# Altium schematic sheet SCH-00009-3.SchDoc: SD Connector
size A4
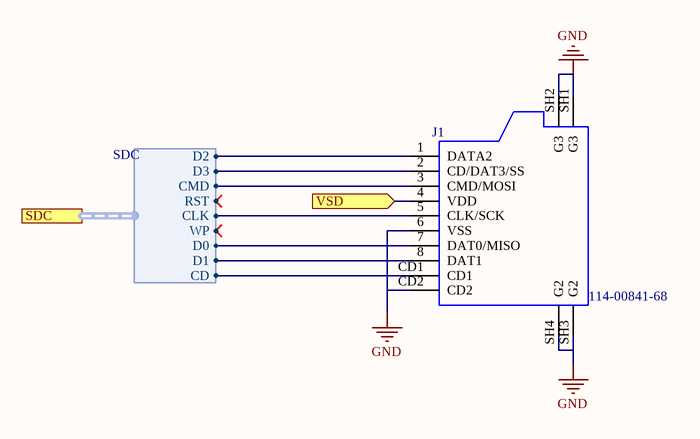
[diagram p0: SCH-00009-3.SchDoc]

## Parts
J1  114-00841-68  [AMPHENOL_114-00841-68]

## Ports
SDC (harness SDC), VSD (in)

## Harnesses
SDC: D0, D1, D2, D3, CMD, CLK, CD, WP, RST

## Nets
GND: J1.6(VSS) J1.CD2 J1.SH1(G3) J1.SH2(G3) J1.SH3(G2) J1.SH4(G2)
VSD: J1.4(VDD) ; port VSD
NetJ1_1: J1.1(DATA2) ; port SDC.D2
NetJ1_2: J1.2(CD/DAT3/SS) ; port SDC.D3
NetJ1_3: J1.3(CMD/MOSI) ; port SDC.CMD
NetJ1_5: J1.5(CLK/SCK) ; port SDC.CLK
NetJ1_7: J1.7(DAT0/MISO) ; port SDC.D0
NetJ1_8: J1.8(DAT1) ; port SDC.D1
NetJ1_CD1: J1.CD1 ; port SDC.CD

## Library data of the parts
J1 = J0011-A.1: CONN Micro SD; Manufacturer: Amphenol; Code Arduino: A5328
